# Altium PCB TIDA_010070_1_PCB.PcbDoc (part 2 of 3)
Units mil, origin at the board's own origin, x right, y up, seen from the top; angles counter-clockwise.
Board outline 3224 x 3643 mil, 4 copper layers (Top Layer, Ground, Power, Bottom Layer), stack 90.4 mil thick; 156 components, 57 nets, 333 pads, 411 vias.
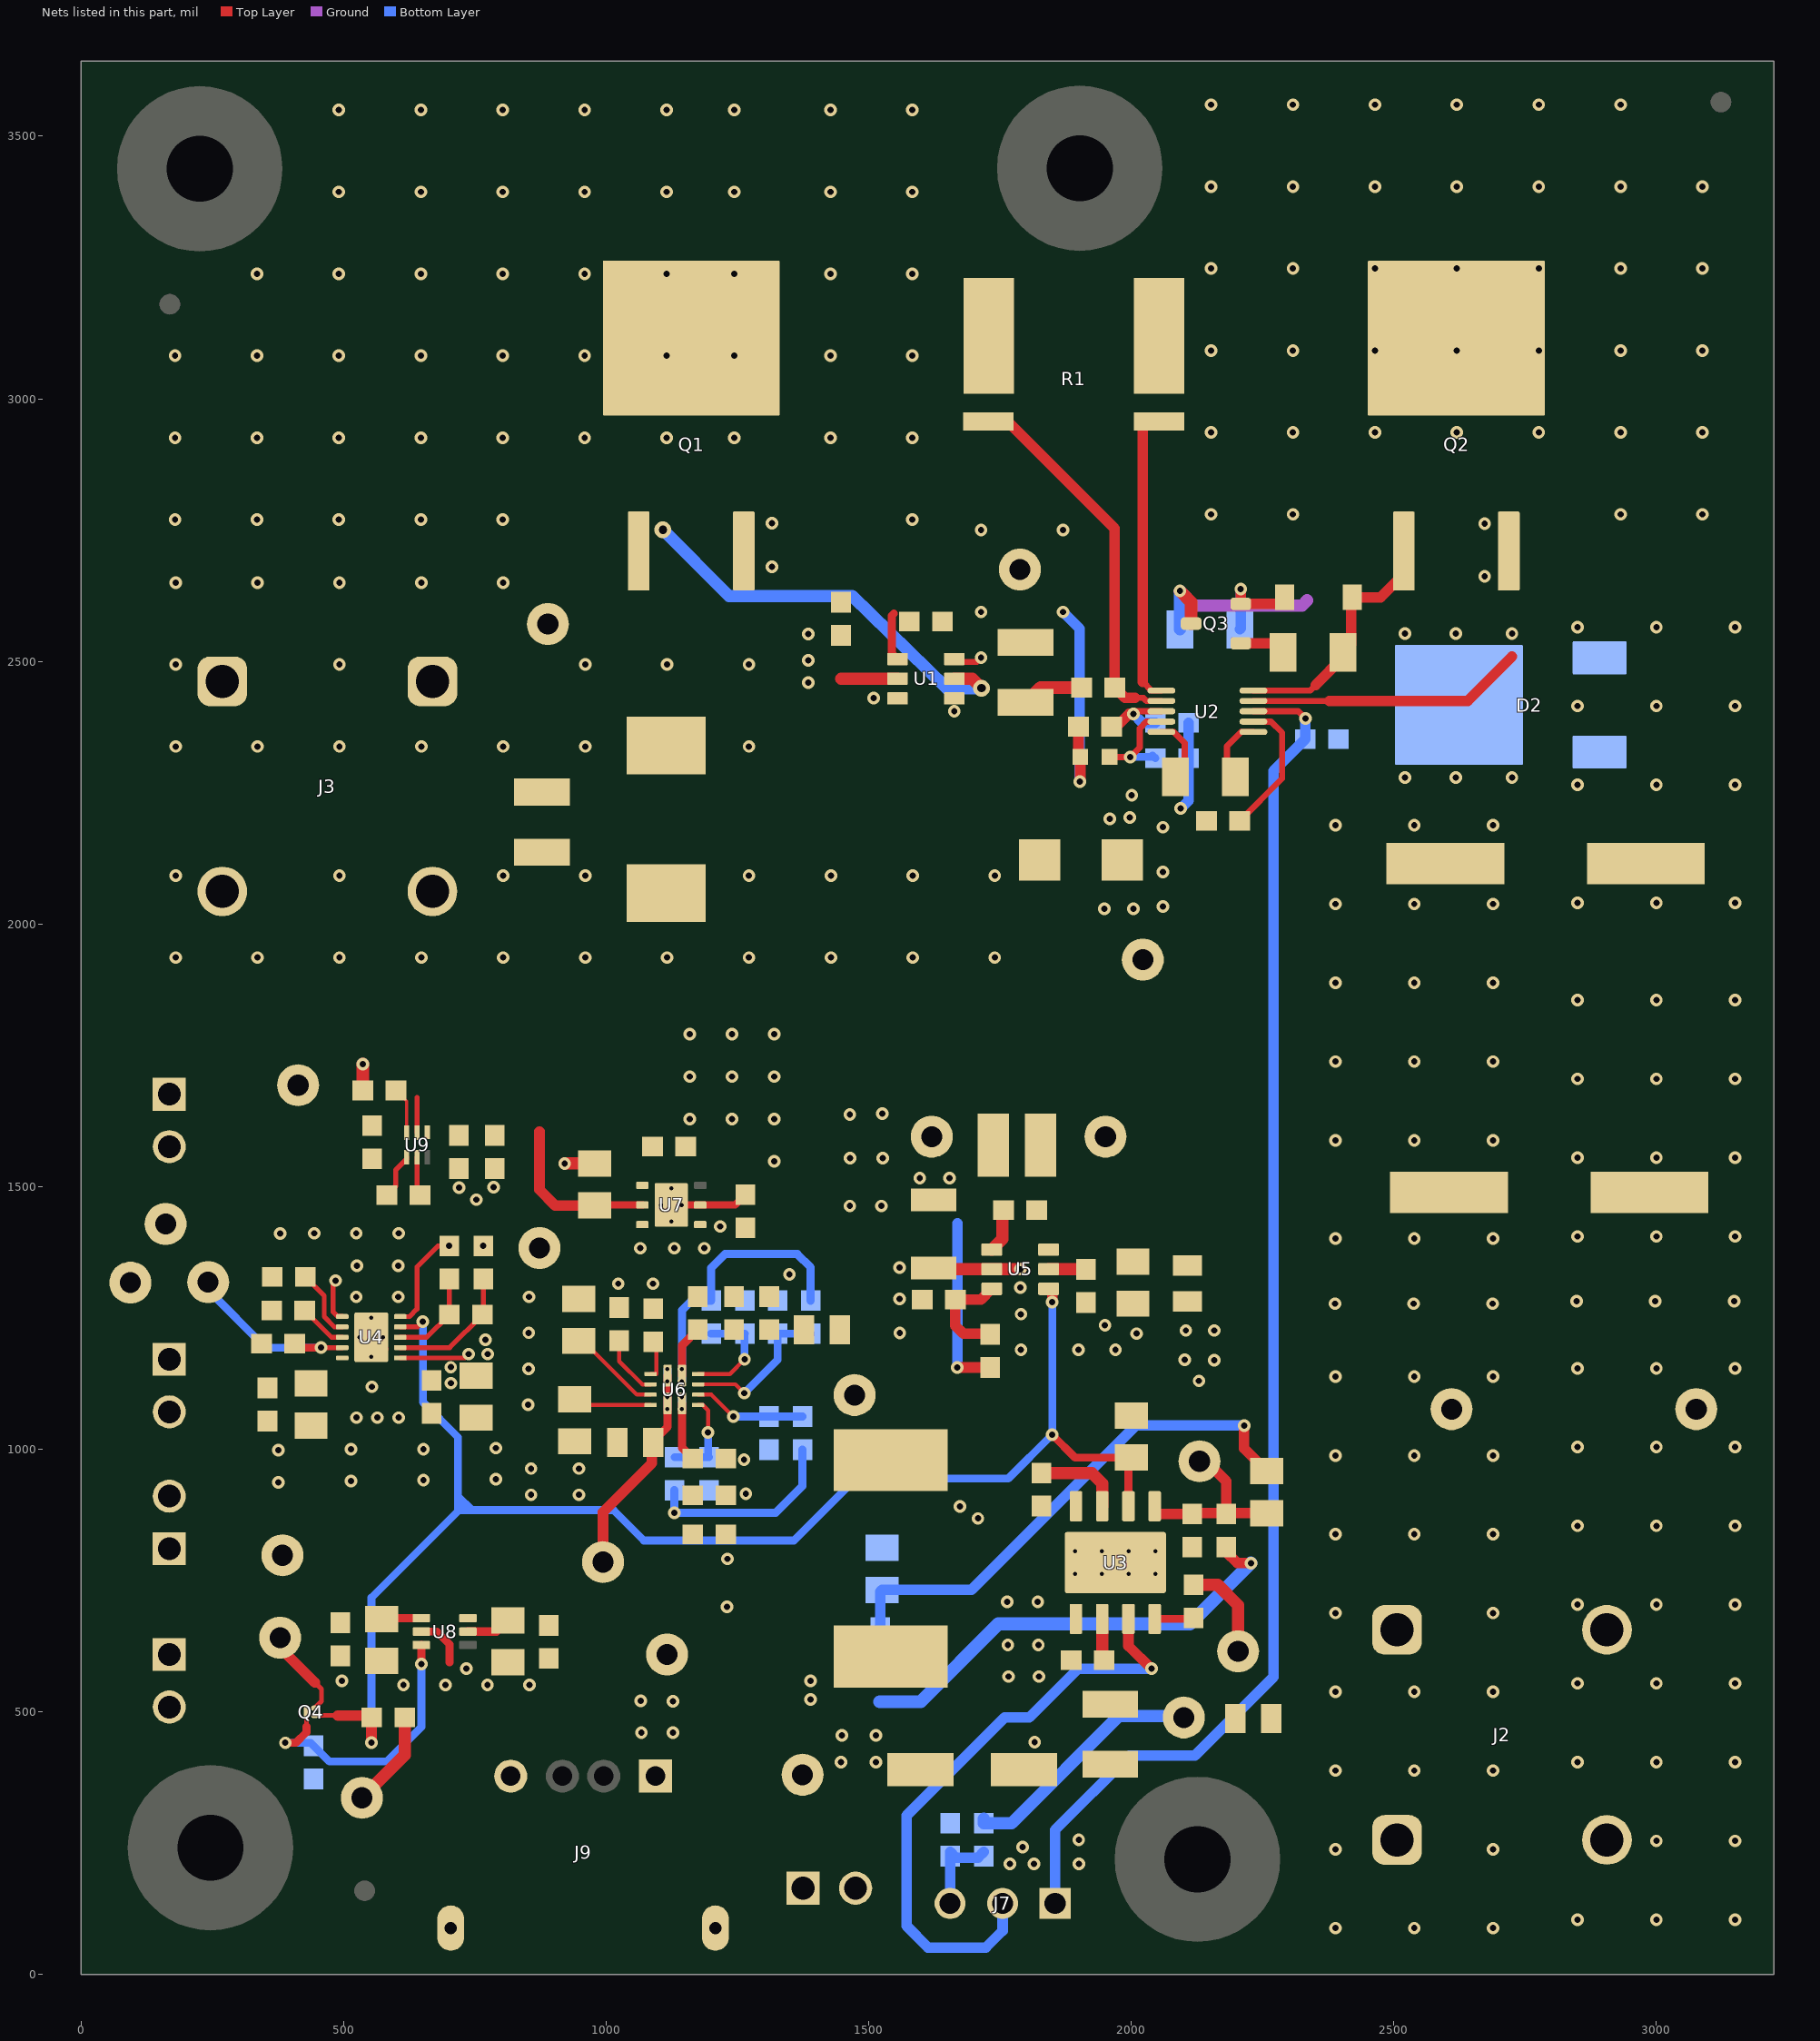
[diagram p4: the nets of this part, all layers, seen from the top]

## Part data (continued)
Q3: library part CMP-0000333-2, "Transistor, PNP, 150 V, 0.5 A, SOT-23", Manufacturer="ON Semiconductor", Supplier Part Number 1=MMBT5401LT1GOSCT-ND, Value1="0.5 A", Value2=240
Q4: library part CMP-0078322-2, "MOSFET, P-CH, -20 V, -3.6 A, YJN0003A (PICOSTAR-3)", Alternate Manufacturer=None, Manufacturer="Texas Instruments", Value1="0.076 ohm", Value2="1.02 nC"
R1: library part CMP-0015295-2, "RES, 0.002, 1%, 3 W, AEC-Q200 Grade 0, 4026", Manufacturer=Vishay-Dale, Power_W=3W, Supplier Part Number 1=WSLR-.002CT-ND, TempCo="75 ppm/C", Tolerance_%=1%, Value_Code=2L000, ValueDisplayed=0.002
R3: library part CMP-0021992-4, "RES, 102 k, 1%, 0.1 W, AEC-Q200 Grade 0, 0603", Manufacturer=Vishay-Dale, Power_W=100mW, Supplier Part Number 1=541-102KHCT-ND, TempCo="100 ppm/C", Tolerance_%=1%, Value2=0.1W, Value_Code=102k
R5: "RES, 95.3k ohm, 1%, 0.1W, 0603", Manufacturer=Vishay-Dale, Power_W=0.1, Supplier Part Number 1=541-95.3KHCT-ND, TempCo="100 ppm/C", Tolerance_%=1, Value1=1%, Value2=0.1W, Value_Code=95k3
R6: library part CMP-0024540-3, "RES, 95.3 k, 0.1%, 0.1 W, 0603", Manufacturer="Yageo America", Power_W=100mW, TempCo="25 ppm/C", Tolerance_%=0.1%, Value2=0.1W, Value_Code=95k3, ValueDisplayed=95.3k
R7: "RES, 100 ohm, 1%, 0.1W, 0603", Manufacturer=Vishay-Dale, Power_W=0.1, Supplier Part Number 1=541-100HCT-ND, TempCo="100 ppm/C", Tolerance_%=1, Value1=1%, Value2=0.1W, Value_Code=100R
R8: library part CMP-0022450-4, "RES, 4.12 k, 1%, 0.1 W, AEC-Q200 Grade 0, 0603", Manufacturer=Vishay-Dale, Power_W=100mW, Supplier Part Number 1=541-4.12KHCT-ND, TempCo="100 ppm/C", Tolerance_%=1%, Value2=0.1W, Value_Code=4k12, ValueDisplayed=4.12k
R9: library part CMP-0023594-3, "RES, 7.15 k, 0.1%, 0.1 W, 0603", Manufacturer="Susumu Co Ltd", Power_W=100mW, Supplier Part Number 1=RG16P7.15KBCT-ND, TempCo="25 ppm/C", Tolerance_%=0.1%, Value2=0.1W, Value_Code=7k15, ValueDisplayed=7.15k
R10: library part CMP-0023508-3, "RES, 30.0 k, 0.1%, 0.1 W, 0603", Manufacturer="Susumu Co Ltd", Power_W=100mW, Supplier Part Number 1=RG16P30.0KBCT-ND, TempCo="25 ppm/C", Tolerance_%=0.1%, Value2=0.1W, Value_Code=30k0, ValueDisplayed=30.0k
R11: library part CMP-0017964-2, "RES, 1.02 k, 1%, 0.25 W, 1206", Manufacturer="Yageo America", Power_W=250mW, Supplier Part Number 1=311-1.02KFRCT-ND, TempCo="100 ppm/C", Tolerance_%=1%, Value2=0.25W, Value_Code=1k02, ValueDisplayed=1.02k
R12: library part CMP-0021080-3, "RES, 25.5 k, 1%, 0.125 W, AEC-Q200 Grade 0, 0805", Manufacturer=Vishay-Dale, Power_W=125mW, Supplier Part Number 1=541-25.5KCCT-ND, TempCo="100 ppm/C", Tolerance_%=1%, Value2=0.125W, Value_Code=25k5, ValueDisplayed=25.5k
R13 R20 R28 R31: library part CMP-0020833-2, "RES, 0, 1%, 0.5 W, 0805", Manufacturer=Keystone, Power_W=500mW, Supplier Part Number 1=36-5106CT-ND, TempCo=ppm/C, Tolerance_%=1%, Value2=0.5W, Value_Code=0
R14: library part CMP-0021713-3, "RES, 422 k, 1%, 0.125 W, AEC-Q200 Grade 0, 0805", Manufacturer=Panasonic, Power_W=125mW, Supplier Part Number 1=P422KCCT-ND, TempCo="100 ppm/C", Tolerance_%=1%, Value2=0.125W, Value_Code=422k
R15: library part CMP-0022010-4, "RES, 113 k, 1%, 0.1 W, AEC-Q200 Grade 0, 0603", Manufacturer=Vishay-Dale, Power_W=100mW, Supplier Part Number 1=541-113KHCT-ND, TempCo="100 ppm/C", Tolerance_%=1%, Value2=0.1W, Value_Code=113k
R16: library part CMP-0023189-4, "RES, 576 k, 1%, 0.1 W, 0603", Manufacturer=Yageo, Power_W=100mW, Supplier Part Number 1=311-576KHRCT-ND, TempCo="100 ppm/C", Tolerance_%=1%, Value2=0.1W, Value_Code=576k
R17: library part CMP-0022204-4, "RES, 20.0 k, 1%, 0.1 W, AEC-Q200 Grade 0, 0603", Manufacturer=Vishay-Dale, Power_W=100mW, Supplier Part Number 1=541-20.0KHCT-ND, TempCo="100 ppm/C", Tolerance_%=1%, Value2=0.1W, Value_Code=20k0, ValueDisplayed=20.0k
R18: library part CMP-0022095-4, "RES, 187 k, 1%, 0.1 W, AEC-Q200 Grade 0, 0603", Manufacturer=Vishay-Dale, Power_W=100mW, Supplier Part Number 1=541-187KHCT-ND, TempCo="100 ppm/C", Tolerance_%=1%, Value2=0.1W, Value_Code=187k
R19: library part CMP-0023142-5, "RES, 49.9 k, 1%, 0.1 W, 0603", Manufacturer=Yageo, Power_W=100mW, Supplier Part Number 1=311-49.9KHRCT-ND, TempCo="100 ppm/C", Tolerance_%=1%, Value2=0.1W, Value_Code=49k9, ValueDisplayed=49.9k
R21: library part CMP-0022237-4, "RES, 24.9 k, 1%, 0.1 W, AEC-Q200 Grade 0, 0603", Manufacturer=Vishay-Dale, Power_W=100mW, Supplier Part Number 1=541-24.9KHCT-ND, TempCo="100 ppm/C", Tolerance_%=1%, Value2=0.1W, Value_Code=24k9, ValueDisplayed=24.9k
R22: library part CMP-0022447-4, "RES, 49.9 k, 1%, 0.1 W, AEC-Q200 Grade 0, 0603", Manufacturer=Vishay-Dale, Power_W=100mW, Supplier Part Number 1=541-49.9KHCT-ND, TempCo="100 ppm/C", Tolerance_%=1%, Value2=0.1W, Value_Code=49k9, ValueDisplayed=49.9k
R23: library part CMP-0022632-4, "RES, 88.7 k, 1%, 0.1 W, AEC-Q200 Grade 0, 0603", Manufacturer=Vishay-Dale, Power_W=100mW, Supplier Part Number 1=541-88.7KHCT-ND, TempCo="100 ppm/C", Tolerance_%=1%, Value2=0.1W, Value_Code=88k7, ValueDisplayed=88.7k
R24: library part CMP-0022123-4, "RES, 1.40 k, 1%, 0.1 W, AEC-Q200 Grade 0, 0603", Manufacturer=Vishay-Dale, Power_W=100mW, Supplier Part Number 1=541-1.40KHCT-ND, TempCo="100 ppm/C", Tolerance_%=1%, Value2=0.1W, Value_Code=1k40, ValueDisplayed=1.40k
R25: library part CMP-0022220-4, "RES, 22.1 k, 1%, 0.1 W, AEC-Q200 Grade 0, 0603", Manufacturer=Vishay-Dale, Power_W=100mW, Supplier Part Number 1=541-22.1KHCT-ND, TempCo="100 ppm/C", Tolerance_%=1%, Value2=0.1W, Value_Code=22k1, ValueDisplayed=22.1k
R26: library part CMP-0022634-4, "RES, 8.06 k, 1%, 0.1 W, AEC-Q200 Grade 0, 0603", Manufacturer=Vishay-Dale, Power_W=100mW, Supplier Part Number 1=541-8.06KHCT-ND, TempCo="100 ppm/C", Tolerance_%=1%, Value2=0.1W, Value_Code=8k06, ValueDisplayed=8.06k
R27: library part CMP-0022249-4, "RES, 26.7 k, 1%, 0.1 W, AEC-Q200 Grade 0, 0603", Manufacturer=Vishay-Dale, Power_W=100mW, Supplier Part Number 1=541-26.7KHCT-ND, TempCo="100 ppm/C", Tolerance_%=1%, Value2=0.1W, Value_Code=26k7, ValueDisplayed=26.7k
R29 R38: library part CMP-0022229-4, "RES, 23.7 k, 1%, 0.1 W, AEC-Q200 Grade 0, 0603", Manufacturer=Vishay-Dale, Power_W=100mW, Supplier Part Number 1=541-23.7KHCT-ND, TempCo="100 ppm/C", Tolerance_%=1%, Value2=0.1W, Value_Code=23k7, ValueDisplayed=23.7k
R30: library part CMP-0022228-4, "RES, 23.2 k, 1%, 0.1 W, AEC-Q200 Grade 0, 0603", Manufacturer=Vishay-Dale, Power_W=100mW, Supplier Part Number 1=541-23.2KHCT-ND, TempCo="100 ppm/C", Tolerance_%=1%, Value2=0.1W, Value_Code=23k2, ValueDisplayed=23.2k
R32 R39: library part CMP-0022458-4, "RES, 4.99 k, 1%, 0.1 W, AEC-Q200 Grade 0, 0603", Manufacturer=Vishay-Dale, Power_W=100mW, Supplier Part Number 1=541-4.99KHCT-ND, TempCo="100 ppm/C", Tolerance_%=1%, Value2=0.1W, Value_Code=4k99, ValueDisplayed=4.99k
R33: library part CMP-0022043-4, "RES, 13.3 k, 1%, 0.1 W, AEC-Q200 Grade 0, 0603", Manufacturer=Vishay-Dale, Power_W=100mW, Supplier Part Number 1=541-13.3KHCT-ND, TempCo="100 ppm/C", Tolerance_%=1%, Value2=0.1W, Value_Code=13k3, ValueDisplayed=13.3k
R34: library part CMP-0025697-4, "RES, 0, 5%, 0.1 W, AEC-Q200 Grade 0, 0603", Manufacturer=Vishay-Dale, Power_W=100mW, Supplier Part Number 1=541-0.0GCT-ND, TempCo="200 ppm/C", Tolerance_%=5%, Value2=0.1W, Value_Code=0000, ValueDisplayed=0
R35: library part CMP-0022564-4, "RES, 6.98 k, 1%, 0.1 W, AEC-Q200 Grade 0, 0603", Manufacturer=Vishay-Dale, Power_W=100mW, Supplier Part Number 1=541-6.98KHCT-ND, TempCo="100 ppm/C", Tolerance_%=1%, Value2=0.1W, Value_Code=6k98, ValueDisplayed=6.98k
R36: library part CMP-0022055-4, "RES, 14.3 k, 1%, 0.1 W, AEC-Q200 Grade 0, 0603", Manufacturer=Vishay-Dale, Power_W=100mW, Supplier Part Number 1=541-14.3KHCT-ND, TempCo="100 ppm/C", Tolerance_%=1%, Value2=0.1W, Value_Code=14k3, ValueDisplayed=14.3k
R37: library part CMP-0022482-4, "RES, 51.1 k, 1%, 0.1 W, AEC-Q200 Grade 0, 0603", Manufacturer=Vishay-Dale, Power_W=100mW, Supplier Part Number 1=541-51.1KHCT-ND, TempCo="100 ppm/C", Tolerance_%=1%, Value2=0.1W, Value_Code=51k1, ValueDisplayed=51.1k
R40: library part CMP-0021998-4, "RES, 10.0 k, 1%, 0.1 W, AEC-Q200 Grade 0, 0603", Manufacturer=Vishay-Dale, Power_W=100mW, Supplier Part Number 1=541-10.0KHCT-ND, TempCo="100 ppm/C", Tolerance_%=1%, Value2=0.1W, Value_Code=10k0, ValueDisplayed=10.0k
R41: library part CMP-0022032-4, "RES, 12.7 k, 1%, 0.1 W, AEC-Q200 Grade 0, 0603", Manufacturer=Vishay-Dale, Power_W=100mW, Supplier Part Number 1=541-12.7KHCT-ND, TempCo="100 ppm/C", Tolerance_%=1%, Value2=0.1W, Value_Code=12k7, ValueDisplayed=12.7k
R42: library part CMP-0021999-4, "RES, 10.2 k, 1%, 0.1 W, AEC-Q200 Grade 0, 0603", Manufacturer=Vishay-Dale, Power_W=100mW, Supplier Part Number 1=541-10.2KHCT-ND, TempCo="100 ppm/C", Tolerance_%=1%, Value2=0.1W, Value_Code=10k2, ValueDisplayed=10.2k
RESET TP1 TP2 TP3 TP5 TP6 TP7 TP8 TP10 TP11 TP12 TP13 TP14 TP15 TP17 TP19 TP20: library part CMP-0055137-1, "Test Point, Miniature, Red, TH", Color=Red, Manufacturer=Keystone, Supplier Part Number 1=36-5000-ND
TP4 TP9 TP16 TP18 TP22: library part CMP-0055138-1, "Test Point, Miniature, Black, TH", Color=Black, Manufacturer=Keystone, Supplier Part Number 1=36-5001-ND
U1: library part CMP-0066129-2, "High Side OR-ing FET Controller, DDC0006A (SOT-23-T-6)", Alternate Manufacturer="Texas Instruments"
U2: library part CMP-0071871-1, "Positive High Voltage Hot Swap / Inrush Current Controller with Power Limiting, 10-pin MSOP, Pb-Free", Manufacturer="Texas Instruments", PackageTopMarking=ZXTT*SNBB, PowerWise=N
U3: library part CMP-0080798-1, "100-V Low IQ Synchronous Buck Regulator, DDA0008E (SOIC-8)", Alternate Manufacturer="Texas Instruments"
U4: library part CMP-0013395-7, "60-V, 800-mA Industrial eFuse with Integrated Reverse Polarity Protection, DRC0010J (VSON-10)", Alternate Manufacturer="Texas Instruments", Alternate PartNumber=TPS26625DRCT, Operating Temperature Range="-40 to 125 C", Rating=Catalog
U5: library part CMP-0065101-2, "4V to 36 V 0.6 A Synchronous Step-Down Converter, DBV0006A (SOT-23-6)", Alternate Manufacturer="Texas Instruments", Alternate PartNumber=TPS560430YDBVT
U6: library part CMP-0078351-3, "2.7V-22V, 4A, 50mohm Priority Power MUX, RUX0012A (VQFN-HR-12)", Alternate Manufacturer="Texas Instruments", Alternate PartNumber=TPS2121RUXT
U7: library part CMP-0070735-1, "500mA Low Dropout CMOS Linear Regulators Stable with Ceramic Output Capacitors, 6-pin LLP, Pb-Free, 1000 Reel", Manufacturer="Texas Instruments", PackageTopMarking=ZXYTT*L120B, PowerWise=Y
U8: library part CMP-0081108-1, "5.5-V, 1.5-A, 100-mohm Load Switch with Output Discharge, DCK0006A (SOT-SC70-6)", Alternate Manufacturer="Texas Instruments", Alternate PartNumber=TPS22919DCKT
U9: library part CMP-0750051-1, "Overvoltage and Undervoltage Reset IC With Time Delay and Manual Reset, DSE0006A (WSON-6)", Alternate Manufacturer="Texas Instruments"
ZZ1: library part CMP-0003616-3
ZZ2: library part CMP-0077236-1
ZZ3: library part CMP-0077237-1
ZZ4: library part CMP-0077238-1

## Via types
v1: diameter 24, hole 12, Top Layer to Bottom Layer, tented both sides, 382 vias
v2: diameter 19.68, hole 7.87, Top Layer to Bottom Layer, 16 vias
v3: diameter 16, hole 8, Top Layer to Bottom Layer, 8 vias
v4: diameter 24, hole 12, Top Layer to Bottom Layer, 3 vias
v5: diameter 32, hole 16, Top Layer to Bottom Layer, tented both sides, 2 vias

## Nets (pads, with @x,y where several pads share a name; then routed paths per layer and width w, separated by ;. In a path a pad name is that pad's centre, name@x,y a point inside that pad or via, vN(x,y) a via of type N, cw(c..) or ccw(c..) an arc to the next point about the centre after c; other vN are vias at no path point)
EN: J7.1 R3.2 U2.8 | length 2632.5
  Top Layer w11.8: U2.8@2232.6,2405 2318,2405 v1(2332,2391)
  Bottom Layer w20: J7.1@1855,135 1855,275 1996.48,416.48 2121.49,416.48 2271,565.99 2271,2291.25 R3.2@2331.5,2351.75 2331.5,2390.5 v1(2332,2391) v1@2332,2391.49
EN/UVLO: J7.2 U3.3 | length 1172
  Top Layer w20: U3.3@1994.62,676.72 1994.62,625.38 2038,582 v1(2039,582)
  Bottom Layer w20: J7.2@1755,135 1755,83 1723,51 1613,51 1572.03,91.97 1572.03,302.32 1758.71,489 1806,489 1899,582 v1(2039,582)
Gate: D5.2 Q2.1 R11.1 U2.10 | length 479
  Top Layer w11.8: U2.10@2232.6,2444.37 2340.37,2444.37 2351,2455
  Top Layer w20: 2351,2455 2403.47,2507.47 R11.1@2403.47,2517 2419,2532.53 2419,2620.06 D5.2@2420.94,2622 2475,2622 2519,2666 Q2.1@2519,2709.98
GND: C1.2 C2.2 C3.1 C4.1 C6.1 C7.2 C8.1 C12.2 C13.2 C14.1 C16.1 C17.2 C18.1 C19.2 C20.1 C21.1 C22.1 C25.1 C26.1 C27.1 C28.1 C29.2 C30.2 C31.1 C32.1 C33.1 C34.1 C35.1 C36.2 C37.1 C38.2 C39.1 C40.2 C41.2 C42.2 C43.2 D2.1 D2.3 D3.1 D4.1 J1.2 J2.2 J3.2 J4.2 J5.2 J6.2 J8.2 J9.4 J9.5 J9.6 Q3.3 R8.2 R9.2 R10.1 R17.2 R18.2 R19.2 R25.2 R32.2 R33.2 R34.2 R35.2 R37.2 R39.2 R41.2 R42.2 TP4.1 TP9.1 TP16.1 TP18.1 TP22.1 U2.5 U3.1 U3.9@1969.62,784 U4.6 U5.2 U6.12 U7.2 U7.7 U8.2 U9.5 | length 2093.2
  Top Layer w7.8: C28.1@950.95,1084.05 U6.12@1084.46,1084.05
  Top Layer w9.45: v1(485,1321) 480.02,1316.02 480.02,1261.34 489,1252.37 U4.6@497.52,1252.37
  Top Layer w9.8: U9.5@639.69,1555.53 639.69,1489.74 C42.2@645.5,1483.93 C42.2@654.43,1475
  Top Layer w11.8: U2.5@2057.4,2365.63 2081,2365.63 2102,2344.63 2102,2298.17 C6.1@2083.91,2280.09 C6.1@2083.91,2266.84
  Top Layer w13.78: v2(1143.68,1464.91) U7.2@1179.12,1464.91 1245.5,1464.91 C29.2@1265,1484.41
  Top Layer w15: U8.2@648.03,652.58 677.55,652.58 701.81,628.32 701.81,594
  Top Layer w23.62: TP22.1@535,336 616.61,417.61 R41.2@616.61,489 ; C43.2@536.5,1683 v4(536.5,1733.41) ; v1(921,1544) C31.1@978,1544 ; C26.1@1310.5,1290.5 C26.1@1310.5,1291.5 ; C22.1@1623.46,1344.89 1625.74,1342.62 U5.2@1734.33,1342.62 v1(1789,1342.62) ; C4.1@1799,2421.91 1827.09,2450 C7.2@1905.5,2450 ; U3.9@1894.62,808 1918.62,784 U3.9@1969.62,784 ; v1(2092.71,2634) 2114.04,2612.68 Q3.3@2114.04,2572 ; R18.2@2119,741.5 2164.81,741.5 2203.45,702.86 TP9.1@2203.45,615
  Ground w23.62: v1(2092.71,2634) 2120.52,2606.19 2325.21,2606.19 2335.02,2616
  Bottom Layer w20: v4(2094.25,2220) 2109.02,2234.77 R8.2@2109.02,2315.52 ; R8.2@2109.02,2315.52 R9.2@2109,2383
  Bottom Layer w23.62: v1(2092.71,2634) 2092.78,2633.94 C8.1@2092.78,2561
  other v1: 2850,104 3000,104 3150,104 1769,210 1815,210 1900.19,210 1793,242 3000,254 3150,254 1900,256 2850,404 3000,404 3150,404 1816,442 614,551 694,551 774,551 854,551 2850,554 3000,554 3150,554 496.52,559 1766,567 1824,567 734,582 1765,627 1823,627 1229.99,699.45 2850,704 3000,704 3150,704 1764,709 1822,709 1230.7,791 2850,854 3000,854 3150,854 1266,915 376,937 514,939 652,941 790,943 1262.5,980 376,998 514,1000 652,1000 790,1002 2850,1004 3000,1004 3150,1004 851.63,1084.65 852.09,1153.1 2850,1154 3000,1154 3150,1154 1790.01,1189 1899.33,1189 1970,1189 2010,1220 852.54,1221.55 1559.19,1221 1950,1236 1790.01,1257 2848,1282 2998,1282 3148,1282 1559,1286 853,1290 1789,1308 1023,1315 1089.28,1315 1349,1333 1559,1346 2850,1405 3000,1405 3150,1405 752.64,1475 720,1498 785.68,1499 1320.17,1548.25 2850,1555 3000,1555 3150,1555 1159,1628.83 1239.58,1628.83 1320.17,1628.83 2850,1705 3000,1705 3150,1705 1159,1709.42 1239.58,1709.42 1320.17,1709.42 1159,1790 1239.58,1790 1320.17,1790 2850,1855 3000,1855 3150,1855 180,1936 336,1936 492,1936 648,1936 804,1936 960,1936 1116,1936 1272,1936 1428,1936 1584,1936 1740,1936 2850,2040 3000,2040 3150,2040 180,2092 492,2092 804,2092 960,2092 1272,2092 1428,2092 1584,2092 1740,2092 2850,2265 3000,2265 3150,2265 2850,2415 3000,2415 3150,2415 2850,2565 3000,2565 3150,2565
  other v2: 1892.85,762.35 1944.03,762.35 1995.21,762.35 2046.39,762.35 1892.85,805.62 1944.03,805.65 1995.21,805.65 2046.39,805.65 1124,1433.42 1104.31,1464.91 1124,1496.41
NetC3_2: C3.2 D3.2 J3.1 Q1.3 TP1.1 U1.4
  other v1: 180,2338 336,2338 492,2338 648,2338 804,2338 960,2338 1272,2338 1663,2405 180,2494 492,2494 960,2494 1116,2494 1272,2494 180,2650 336,2650 492,2650 648,2650 804,2650 1316,2680 1316,2762.83
NetC4_2: C4.2 H15.1 Q1.2 R1.2 R5.2 R6.2 R7.1 TP2.1 U1.6 | length 499.3
  Top Layer w11.8: U1.6@1663.13,2504.35 1668.48,2499 1706,2499 v1@1714,2507
  Top Layer w20: R6.2@1899.43,2375.75 1899.43,2321.5 R5.2@1902.93,2318 1902.93,2271.93 v1(1902,2271)
  Bottom Layer w20: v1(1869.94,2594.04) 1902,2561.98 v1(1902,2271)
  other v1: 1713.94,2507 1713.94,2594.04 1713.94,2750.04 1869.94,2750.04 179,2770 335,2770 491,2770 647,2770 803,2770 1583,2770 179,2926 335,2926 491,2926 647,2926 803,2926 959,2926 1115,2926 1244,2926 1427,2926 1583,2926 179,3082 335,3082 491,3082 647,3082 803,3082 959,3082 1115,3082 1244,3082 1427,3082 1583,3082 335,3238 491,3238 647,3238 803,3238 959,3238 1115,3238 1244,3238 1427,3238 1583,3238 491,3394 647,3394 803,3394 959,3394 1115,3394 1244,3394 1427,3394 1583,3394 491,3550 647,3550 803,3550 959,3550 1115,3550 1244,3550 1427,3550 1583,3550
NetC5_1: C5.1 R7.2 U1.1 | length 92.8
  Top Layer w15: 1547.98,2591 1544,2587.02 1544,2515.21 U1.1@1554.87,2504.35
NetC5_2: C5.2 D4.2 U1.2 U1.3 | length 107
  Top Layer w23.62: 1447.84,2466.94 U1.2@1554.87,2466.94
  other v1: 1948.9,2028.75 2004,2029 2060,2033 2060,2099.25 2060,2184.25 1959,2200 1997,2203 2001,2245 1509.48,2430 1385,2459.74 1385,2502 1385,2552
NetC6_2: C6.2 U2.6 | length 126.9
  Top Layer w11.8: C6.2@2198.09,2280.09 2182,2296.17 2182,2338.54 2209.09,2365.63 U2.6@2232.6,2365.63
NetC7_1: C7.1 R1.4 U2.2 | length 727
  Top Layer w11.8: 2007,2430.46 2022.92,2430.46 2028.69,2424.69 U2.2@2057.4,2424.69
  Top Layer w20: R1.4@1728.2,2956.64 1764.87,2956.64 1968.5,2753.02 C7.1@1968.5,2450 1988.04,2430.46 2007,2430.46
NetC8_2: C8.2 D5.1 Q3.2 | length 194.9
  Top Layer w20: v1(2208.52,2638) Q3.2@2208.52,2609.4 2279.4,2609.4 D5.1@2292,2622
  Bottom Layer w20: C8.2@2206.95,2561 2208.52,2562.57 v1(2208.52,2638)
NetC9_1: C9.1 L1.1 R14.1 TP6.1 U3.8
  other v1: 1708,868 1674,891
NetC9_2: C9.2 U3.7 | length 161.2
  Top Layer w23.2: C9.2@1835,954.28 1925.16,954.28 1944.62,934.82 U3.7@1944.62,891.28
NetC10_2: C10.2 C11.2 R14.2 | length 997
  Top Layer w20: v4(2215,1045) 2215,1001.1 C11.2@2258,958.1
  Bottom Layer w20: C10.2@1522,660.33 1522,728.47 R14.2@1525.53,732 1696,732 2009,1045 v4(2215,1045)
NetC11_1: C11.1 R16.2 R19.1 TP8.1 U3.5 | length 360.2
  Top Layer w20: U3.5@2044.62,891.28 2044.62,876.5 R19.1@2116,876.5 2117.5,878 R16.2@2181,878 ; TP8.1@2130,977 2143,977 2181,939 R16.2@2181,878 ; C11.1@2258,878 R16.2@2182.5,878 ; R16.2@2181,878 R16.2@2182.5,878 ; R16.2@2181,878 R16.2@2181,876.5 R16.2@2182.5,878
NetC12_1: C12.1 C14.2 R13.2 R15.1 TP5.1 U3.2 | length 533.7
  Top Layer w23.62: C12.1@1944.62,597.8 U3.2@1944.62,676.72
  Bottom Layer w23.62: R15.1@1719,295.99 R15.1@1719,287.74 1772.12,287.74 1976.38,492 TP5.1@2080.92,492
NetC15_1: C15.1 U5.1 | length 84.2
  Top Layer w23.62: U5.1@1734.33,1380.02 1754.46,1400.15 1754.46,1452.35 C15.1@1756.97,1454.85
NetC15_2: C15.2 L2.1 TP11.1 U5.6
NetC20_2: C20.2 C21.2 R20.2 U5.5 | length 71
  Top Layer w23.62: U5.5@1842.6,1342.62 1913.13,1342.62 C21.2@1913.46,1342.28
NetC23_1: C23.1 U4.8 | length 92.6
  Top Layer w9: C23.1@426,1264 477,1213 U4.8@497.52,1213
NetC23_2: C23.2 R26.2 R27.2 U4.5 U4.11 | length 279.4
  Top Layer w9.4: U4.5@607.76,1252.37 625.44,1252.37 639.69,1266.62 639.69,1346.69 679.99,1386.99 v1(701,1386.99)
  Top Layer w9.45: U4.11@528.9,1189.26 U4.11@552.64,1213 U4.11@552.64,1231.28
  Top Layer w20: U4.11@552.64,1213 U4.11@575,1190.64
  other v1: 524.66,1060 564,1060 605,1060 554,1118.76 524,1290 604,1290 525.12,1349 604,1349 379,1410.28 444.01,1411 524.06,1411 605,1411
  other v2: 552.64,1175.6 530,1213 575.28,1213 552.64,1250.4
NetC25_2: C25.2 C26.2 C27.2 R28.2 R29.1 R30.1 U6.7 | length 634.3
  Top Layer w15.75: U6.7@1144.5,1140.15 1144.5,1197.5 C27.2@1174.5,1227.5
  Bottom Layer w15.75: v3(1144.26,1129.34) v3(1144.26,1152.34) 1144.26,1264.26 1162.99,1282.99 R30.1@1200,1282.99 1200,1345 1226.58,1371.58 1363.91,1371.58 1389.5,1346 R29.1@1389.5,1282.99
NetC28_2: C28.2 C29.1 R31.2 U7.1 U7.6
  other v1: 857,913 948,913 857,963 948,963 1065,1382.55 1130,1382.55 1187,1382.55 1217,1424
NetC32_2: C32.2 U6.11 | length 178.8
  Top Layer w7.78: C32.2@948,1206 956,1206 1058.27,1103.73 U6.11@1084.46,1103.73
NetC43_1: C43.1 U9.3 | length 88.7
  Top Layer w6: C43.1@599.5,1683 620.01,1662.49 U9.3@620.01,1602.77
NetH13_1: H13.1 Q2.2 R1.1
  other v1: 2152,2780 2308,2780 2932,2780 3088,2780 2152,2936 2308,2936 2464,2936 2620,2936 2776,2936 2932,2936 3088,2936 2152,3092 2308,3092 2464,3092 2620,3092 2776,3092 2932,3092 3088,3092 2152,3248 2308,3248 2464,3248 2620,3248 2776,3248 2932,3248 3088,3248 2152,3404 2308,3404 2464,3404 2620,3404 2776,3404 2932,3404 3088,3404 2152,3560 2308,3560 2464,3560 2620,3560 2776,3560 2932,3560
NetQ1_1: Q1.1 U1.5 | length 789.8
  Top Layer w23.62: U1.5@1663.13,2466.94 1697.06,2466.94 v5(1715,2449)
  Bottom Layer w23.62: v5(1108,2750.44) 1233.98,2624.46 1468.29,2624.46 1648.46,2449 v5(1715,2449)
NetQ3_1: Q3.1 R11.2 | length 88.1
  Top Layer w20: Q3.1@2208.52,2534.6 2271.7,2534.6 R11.2@2289.3,2517
NetR1_3: R1.3 U2.1 | length 542.3
  Top Layer w11.8: 2022,2461 2038.63,2444.37 U2.1@2057.4,2444.37
  Top Layer w20: 2022,2461 2022,2946.01 R1.3@2032.63,2956.64
NetR5_1: R5.1 R8.1 U2.4 | length 204.7
  Top Layer w11.8: R5.1@1965.93,2318 v1(1998,2318) ; U2.4@2057.4,2385.32 2028.69,2385.32 2016,2372.62 2016,2336 v1@2000.26,2320.26 ; v1(1998,2318) v1@2000.26,2320.26 ; v1(1998,2318) 2002.52,2318 v1@2000.26,2320.26 ; v1(1998,2318) 1998,2319.48 1999.52,2321 v1@2000.26,2320.26
  Bottom Layer w15: v1(1998,2318) 2037.54,2318 2040.54,2321 R8.1@2046.02,2315.52
NetR6_1: R6.1 R9.1 U2.3 | length 156.1
  Top Layer w11.8: v1(2004,2400) 2008.92,2404.92 2057.32,2404.92 U2.3@2057.4,2405
  Top Layer w20: R6.1@1962.43,2375.75 1971.75,2375.75 1996,2400 v1(2004,2400)
  Bottom Layer w20: v1(2004,2400) 2021,2383 R9.1@2046.01,2383
NetR10_2: R10.2 U2.7 | length 265.1
  Top Layer w11.8: R10.2@2206.5,2196 2287.33,2276.83 2287.33,2364.07 2266.09,2385.32 U2.7@2232.6,2385.32
NetR18_1: R18.1 U3.4 | length 75.1
  Top Layer w15: U3.4@2044.62,676.72 2117.21,676.72 R18.1@2119,678.5
NetR21_2: R21.2 R24.1 U4.2 | length 253.5
  Top Layer w9.4: U4.2@607.76,1193.31 701.81,1193.31 R24.1@764.5,1256 766,1257.5 R21.2@766,1324 ; R21.2@764.5,1330 R21.2@766,1331.5
NetR22_2: R22.2 TP13.1 U4.9 | length 353
  Top Layer w9.45: v1(457,1193.32) U4.9@497.52,1193.32
  Top Layer w15: R22.2@406.71,1201 414.39,1193.32 v1(457,1193.32)
  Bottom Layer w15: TP13.1@243,1302 351.68,1193.32 v1(457,1193.32)
NetR23_2: R23.2 R25.1 U5.3 | length 200.5
  Top Layer w20: R23.2@1731,1218.5 1729.65,1219.85 1680.15,1219.85 1664.96,1235.04 R25.1@1664.96,1284.85 1713.96,1284.85 U5.3@1734.33,1305.21
NetR24_2: R24.2 R26.1 U4.3 | length 180.5
  Top Layer w9.4: U4.3@607.76,1213 658.5,1213 R24.2@701.5,1256 701,1256.5 R26.1@701,1324 ; R26.1@701,1331.5 R26.1@701.5,1331
NetR27_1: R27.1 U4.7 | length 133.3
  Top Layer w9: R27.1@427,1328 463,1292 463,1252.27 482.59,1232.69 U4.7@497.52,1232.69
NetR30_2: R30.2 R33.1 U6.6 | length 213.3
  Top Layer w7.87: U6.6@1175.01,1143.1 1235.61,1143.1 v1(1263.5,1171)
  Bottom Layer w15: R30.2@1200,1220 R33.1@1264,1220 1263.5,1219.5 v1(1263.5,1171)
NetR31_1: R31.1 TP14.1 U6.1 U6.8 | length 482.2
  Top Layer w15.75: R31.1@1087.3,1013 1116.94,1042.64 U6.1@1116.94,1087 U6.8@1116.94,1140.15
  Top Layer w20: TP14.1@994,785 994,880 1087.3,973.3 R31.1@1087.3,1013
  Bottom Layer w15.75: v3(1116.7,1076.19) v3(1116.7,1099.19) v3(1116.7,1129.34) v3(1116.7,1152.34)
NetR34_1: R34.1 U6.9 | length 75.5
  Top Layer w7.87: U6.9@1084.46,1143.1 1096,1143.1 1096,1198.31 R34.1@1089.8,1204.5
NetR35_1: R35.1 R36.1 U6.3 | length 179.4
  Top Layer w7.75: U6.3@1175.01,1084.05 1183.95,1084.05 1194,1074 v1(1194,1031.7)
  Bottom Layer w15: R36.1@1130,984.55 R35.1@1196,984.55 1194,986.55 v1(1194,1031.7)
NetR37_1: R37.1 U6.10 | length 117
  Top Layer w7.87: R37.1@1025,1206.5 1025,1167 1068.58,1123.42 U6.10@1084.46,1123.42
NetR38_2: R38.2 R39.1 U6.4 | length 216.3
  Top Layer w7.8: U6.4@1175.01,1103.73 1200.27,1103.73 v1(1242,1062)
  Bottom Layer w15: v1(1242,1062) R39.1@1310,1062 R38.2@1374,1062
ON: Q4.3 R42.1 U8.3 | length 544.5
  Top Layer w9: 429.25,471.67 Q4.3@429.25,499.89
  Top Layer w15: v1(389.04,440.79) 409.04,440.79 429.25,461 429.25,471.67 ; v1(648,591) U8.3@648.03,626.99
  Bottom Layer w15: v1(389.04,440.79) 437.24,440.79 R42.1@442.82,435.21 473.03,405 581.87,405 648,471.13 v1(648,591)
OV1: R29.2 R32.1 U6.5 | length 297.7
  Top Layer w7.5: U6.5@1175.01,1123.42 1246.17,1123.42 v1(1263,1106.59)
  Bottom Layer w15: v1(1263,1106.59) 1326.5,1170.09 R32.1@1326.5,1220 R29.2@1389.5,1220
PG_LM5164: Q4.1@445,493 R12.1 R41.1 U3.6 U4.4 U5.4 | length 2915.1
  Top Layer w9: Q4.1@445,493 489,493
  Top Layer w9.44: U4.4@607.76,1232.68 640.68,1232.68 v1(651,1243)
  Top Layer w15: v1(1849.49,1027.51) 1893,984 R12.1@2000,984 ; U3.6@1994.62,891.28 R12.1@1994.62,978.62
  Top Layer w20: 489,493 549.62,493 553,489.62 v1(553,441) ; U5.4@1842.6,1305.21 1849.49,1298.32 v1(1849.49,1280)
  Bottom Layer w15: v1(553,441) 553,717 720,884 ; v1(651,1243) 651,1089.45 718,1022.45 718,910 ; v1(1849.49,1280) v1(1849.49,1027.51) 1765.97,944 1475.64,944 1357.64,826 1072,826 1014,884 743,884 ; 718,910 743,885 743,884 ; 718,910 718,886 720,884 ; 720,884 743,884
Rdiv: J7.3 R15.2 R17.1 | length 171
  Bottom Layer w20: J7.3@1655,135 1655,233 1665.75,222.25 1708.36,222.25 R15.2@1719.12,233
Reset: C42.1 R40.1 RESET.1 U9.4 | length 87.1
  Top Layer w10: C42.1@582.5,1483.93 599.45,1500.88 599.45,1531.75 620.01,1552.31 U9.4@620.01,1555.53
V_5VBAT: C36.1 C37.2 J6.1 Q4.2@445,506.78 TP19.1 U8.1 | length 248.7
  Top Layer w9: Q4.2@445,506.78 458,519.78 458,543 445,556
  Top Layer w15: C37.2@572.33,676.58 573.92,678.17 U8.1@648.03,678.17
  Top Layer w20: TP19.1@379,641 379,622 445,556
V_P: C30.1 C31.2 C40.1 C41.1 J8.1 R40.2 TP15.1 U7.4 U7.5 U9.1 U9.2 | length 386
  Top Layer w9.8: U9.2@639.69,1602.77 639.69,1669.31
  Top Layer w13.78: C31.2@978,1464 978.91,1464.91 U7.5@1068.88,1464.91
  Top Layer w20: 873,1604.76 873,1494 903,1464 C31.2@978,1464
VCC_5V_MAINS: C16.2 C17.1 C22.2 L2.2 R21.1 R23.1 R28.1 TP12.1 U4.1 | length 470
  Top Layer w9.4: U4.1@607.76,1173.63 730.63,1173.63 v1(738,1181)
  Top Layer w20: v1(1668.88,1155.69) 1668.88,1155.5 R23.1@1731,1155.5
  Bottom Layer w20: v1(1668.88,1155.69) 1668.88,1430.12
  other v1: 704.06,1125.69 704,1156 774.68,1181 770,1208 766,1386.99 1464,1463 1524.19,1463 1597.19,1516 1654.19,1516 1464.81,1554 1527,1554 1464,1637 1526,1639
VCC_5V_USB: C33.2 C34.2 C35.2 J9.1 R36.2 R38.1 TP17.1 U6.2 | length 513.3
  Top Layer w15.75: U6.2@1144.5,1087 1144.5,1002.5 C35.2@1165,982
  Bottom Layer w15.75: R36.2@1130,921.56 v1(1130,878.94) 1322.94,878.94 1374,930 R38.1@1374,999.01 ; v3(1144.26,1076.19) v3(1144.26,1099.19)
  other v1: 1067.11,460 1127.11,460 1127,520 1066.11,521
VCC_15V: C10.1 C13.1 J5.1 L1.2 R12.2 R16.1 R20.1 TP7.1 | length 881.6
  Top Layer w20: R16.1@2181,813.5 2181,804 2202,783 v1(2228,783)
  Bottom Layer w25: 1521,519 1599,519 1747,667 2112,667 v1(2228,783)
  other v1: 1446.9,404 1514,404 1448.9,455 1514,455 1389,523 1389,559 2129,1130 2158,1169 2102,1170 2104,1226 2158,1226
VCC_48V: C1.1 C2.1 D2.2 J2.1 Q2.3 R3.1 R13.1 TP3.1 U2.9 | length 583.3
  Top Layer w11.8: U2.9@2232.6,2424.69 2377,2424.69
  Top Layer w20: 2377,2424.69 2640.69,2424.69 2725,2509
  Top Layer w30: Q2.3@2719,2709.98 Q2.3@2719,2766
  other v1: 2389,88 2539,88 2689,88 2389,238 2689,238 2389,388 2539,388 2689,388 2389,538 2539,538 2689,538 2389,688 2689,688 2389,838 2539,838 2689,838 2389,988 2539,988 2689,988 2389,1138 2539,1138 2689,1138 2388,1277 2538,1277 2688,1277 2389,1401 2539,1401 2689,1401 2389,1588 2539,1588 2689,1588 2389,1738 2539,1738 2689,1738 2389,1888 2539,1888 2689,1888 2389,2038 2539,2038 2689,2038 2389,2188 2539,2188 2689,2188 2521,2279 2618,2279 2725,2279 2521,2553 2618,2553 2725,2553 2673,2662 2673,2762
VCC_ENC1: C18.2 C19.1 J1.1 R22.1 TP10.1 U4.10
VCC_ENC2: C38.1 C39.2 J4.1 TP20.1 U8.5 U8.6 | length 84.8
  Top Layer w15.78: U8.5@736.62,652.58 791.13,652.58 C39.2@812.54,674
pads on no net: FID1.1 FID2.1 FID3.1 FID4.1 FID5.1 FID6.1 H1.1 H2.1 H3.1 H4.1 H5.0 H6.0 H7.0 H8.0 J9.2 J9.3 Q4.1@445,492.02 Q4.2@445,507.76 U3.9@1969.62,784 U7.3 U8.4 U9.6

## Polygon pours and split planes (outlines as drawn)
NetC5_2 on Top Layer "TOP_LAYER_NETC5_2_P276" (solid, remove dead copper, pour order 276): 2018,2217 2025,2210 2025,2089 2015,2079 1935.27,2079 1930,2084.27 1930,2205 1942,2217
V_P on Top Layer "Top Layer-No Net" (solid, remove dead copper, pour order 160): 70,1820 50,1800 50,1640 60,1630 360,1630 390,1600 585,1600 587,1602 587,1639 585,1641 503.8,1641 494,1650.8 494,1721 504,1731 624,1731 635,1720 635,1662.49 635,1594 644,1585 850,1585 865,1570 878.94,1570 894,1585 1036,1585 1040,1581 1040,1499 1044,1495 1077.17,1495 1077.17,1519.17 1104,1546 1104,1806 1090,1820
NetC5_2 on Top Layer "Top Layer-No Net" (solid, remove dead copper, pour order 90): 1360,2557 1373,2570 1485,2570 1489,2566 1489,2486.56 1499.56,2476 1571.39,2476 1574,2473.39 1574,2421.08 1568.92,2416 1370,2416 1360,2426
NetC3_2 on Top Layer "Top Layer-No Net" (solid, remove dead copper, pour order 88): 970,2680 980,2670 980,2590 990,2580 1000,2580 1200,2580 1220,2600 1220,2780 1230,2790 1330,2790 1340,2780 1340,2594 1340,2387 1361,2366 1609,2366 1644,2401 1644,2441 1679,2441 1679,2236 1663,2220 781.88,2220 764.09,2237.78 711.88,2290 50,2290 40,2300 40,2669.96 50.04,2680
NetH13_1 on Top Layer "Top Layer-No Net" (solid, remove dead copper, pour order 98): 3027.7,3610 3050,3587.7 3050,3500 3060,3490 3187,3490 3189.7,3487.3 3189.7,2690.7 3179,2680 2815,2680 2804,2691 2804,2791 2789,2806 2434,2806 2419,2791 2419,2701.04 2397.96,2680 2125,2680 2114,2691 2114.04,2987.16 2100.95,3000.25 1990,3000.25 1980.81,3009.44 1980.81,3322.81 2060,3402 2060,3590 2080,3610
NetQ1_1 on Top Layer "M1 Board Outline-No Net" (solid, remove dead copper, pour order 218): 1030,2790 1121,2790 1130,2781 1130,2630 1120,2620 1030,2620 1020,2630 1020,2780
GND on Top Layer "Top Layer-No Net" (solid, remove dead copper, pour order 158): 1338.68,1468.49 1254.79,1468.49 1246.3,1460 1220,1460 1220,1469 1235.5,1469 1240,1473.5 1240,1540 1230,1550 1140,1550 1130,1560 1130,1810 1140,1820 1340,1820 1350,1810 1350,1542 1350,1479.81
NetC28_2 on Top Layer "Top Layer-No Net" (solid, remove dead copper, pour order 156): 1035,1367 1043,1359 1285.5,1359 1290,1363.5 1290,1439 1286,1443 1174,1443 1166,1435 1166,1424 1162,1420 1085,1420 1081,1424 1081,1429 1074,1436 1038,1436 1035,1433
GND on Top Layer "Top Layer-No Net" (solid, remove dead copper, pour order 152): 1310,1331 1316,1337 1316,1365 1321,1370 1380,1370 1390,1360 1390,1282.25 1378.67,1271.08 1344,1271 1142.94,1271 1116.94,1245 975,1245 960,1260 913,1260 894,1241 894,1151 904,1141 984,1141 994,1131 994,1097 1003,1088 1019,1088 1019,1080 1004.81,1080 985.81,1061 824,1061 814,1071 814,1431 824,1441 920.95,1441 931,1430.95 931,1339 939,1331
NetC28_2 on Top Layer "Top Layer-No Net" (solid, remove dead copper, pour order 150): 835.51,1035.51 888.02,1035.51 893.51,1041 1043,1041 1046,1038 1046,976 960,890 840,890 830,900 830,1030
NetC25_2 on Top Layer "Top Layer-No Net" (solid, remove dead copper, pour order 148): 1340,1189.99 1388.4,1189.99 1394.41,1196 1394.41,1246.65 1390.06,1251 1158,1251 1140,1233 1140,1202 1144.5,1197.5 1146.99,1200 1329.99,1200
GND on Top Layer "Top Layer-No Net" (solid, remove dead copper, pour order 146): 670,50.95 681,40 1270,40 1284,54 1284,699 1284,991 1274,1001 1204.46,1001 1204.46,314.46 1180,290 880,290 860,310 860,410 850,420 680,420 670,410
VCC_5V_USB on Top Layer "Top Layer-No Net" (solid, remove dead copper, pour order 144): 1050,403 1000,453 1000,703 1050,753 1050,898 1134,982 1134,1026 1142,1034 1150,1034 1181,1003 1184,1003 1184,343.88 1170.12,330 1059,330 1050,339
GND on Top Layer "Top Layer-No Net" (solid, remove dead copper, pour order 142): 2036,1302 2040,1298 2040,1170 2030,1160 1780,1160 1770,1170 1770,1360 1810,1360 1810,1259.75 1819.75,1250 1880,1250 1889.98,1259.98 1889.96,1279.77 1899.33,1289.14 1943.38,1289.14 1953.24,1299 1968.19,1299 1971.19,1302
GND on Top Layer "Top Layer-No Net" (solid, remove dead copper, pour order 140): 1547.88,1369 1540.19,1361.32 1540.19,1199 1548.19,1191 1621.19,1191 1624.19,1194 1624.19,1313 1627.19,1316 1674.19,1316 1695,1336.81 1695,1348.19 1674.19,1369
VCC_5V_MAINS on Top Layer "Top Layer-No Net" (solid, remove dead copper, pour order 138): 1419.9,1370.1 1419.9,1200.1 1430,1190 1500.41,1190 1510.68,1200.27 1510.68,1251.06 1510.41,1419.21 1537.19,1446 1673.19,1446 1676.19,1449 1676.19,1513 1679.19,1516 1767.19,1516 1767.19,1660.12 1756.46,1670.85 1400.46,1670.85 1390.46,1660.85 1390.46,1399.54
NetC15_2 on Top Layer "Top Layer-No Net" (solid, remove dead copper, pour order 136): 2013.19,1666 2024.19,1655 2024.19,1536 2014.19,1526 1884,1526 1874.19,1516 1874.19,1384 1860.19,1370 1820.15,1370 1794.19,1395.95 1794.19,1655.93 1804.26,1666
VCC_15V on Top Layer "Top Layer-No Net" (solid, remove dead copper, pour order 134): 2074.19,1140 2064.19,1130 1950,1130 1940,1120 1940,1050 1950,1040 2170,1040 2182.55,1052.55 2182.55,1295.45 2177.49,1300.51 2080.19,1300.51 2074.19,1294.52
NetC20_2 on Top Layer "Top Layer-No Net" (solid, remove dead copper, pour order 132): 1884.19,1356 1914.19,1386 2145.19,1386 2154.19,1377 2154.19,1336 2144.19,1326 1944.19,1326 1940.19,1322 1887.95,1322 1883.95,1326
GND on Top Layer "Top Layer-No Net" (solid, remove dead copper, pour order 130): 1895.13,569.13 1880,554 1880,429.96 1889.96,420 2003,420 2013.15,409.85 2013.15,373.15 1970,330 1883,330 1740,330 1730,340 1730,740 1770,780 1819,780 1881,842 2064.27,842 2132,842 2137,837 2137,726 2132,721 1914,721 1902,709 1902,576
VCC_15V on Top Layer "Top Layer-No Net" (solid, remove dead copper, pour order 128): 1660,650 1640,670 1329,670 1310,651 1310,100 1320,90 1410,90 1419.95,99.95 1419.95,318.95 1441,340 1640,340 1660,360
NetC9_1 on Top Layer "Top Layer-No Net" (solid, remove dead copper, pour order 126): 1374,1092 1374,1094 1374,1143.9 1390.1,1160 1550,1160 1560,1150 1560,1081 1571,1070 1751,1070 1771,1050 1771,944 1797,919 1906,919 1914,911 1914,871 1904,861 1854,861 1814,821 1394,821 1374,841
NetC12_1 on Top Layer "Top Layer-No Net" (solid, remove dead copper, pour order 124): 2068.22,420 2039.96,420 2030,429.96 2030.11,458.11 2018.22,470 1957.89,470 1920,470 1905.78,484.22 1905.78,537.99 1928,560.22 1928,624 1947,643 1948,643 1969,622 1969,612 2040,541 2210,541 2220,531 2220,440 2200,420
GND on Top Layer "Top Layer-No Net" (solid, remove dead copper, pour order 106): 1805.84,1900 1849.84,1856 2084,1856 2164.55,1936.55 2164.55,2247.05 2123,2288.6 2123,2343 2096,2370 2036.73,2370 2032,2365.27 2032,2246.96 2092,2186.96 2092,2031 2063,2002 1906.47,2002 1889.96,2017 1889.96,2160 1853,2196.96 1853,2411.78 1863.95,2422.73 1913.12,2422.73 1923.39,2433 1923,2433.39 1923,2465 1920,2468 1833,2468 1829,2464 1766,2464 1744,2442 1744,2230 1685,2171 80,2171 60,2151 40,2131 40,1920 60,1900 145,1900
